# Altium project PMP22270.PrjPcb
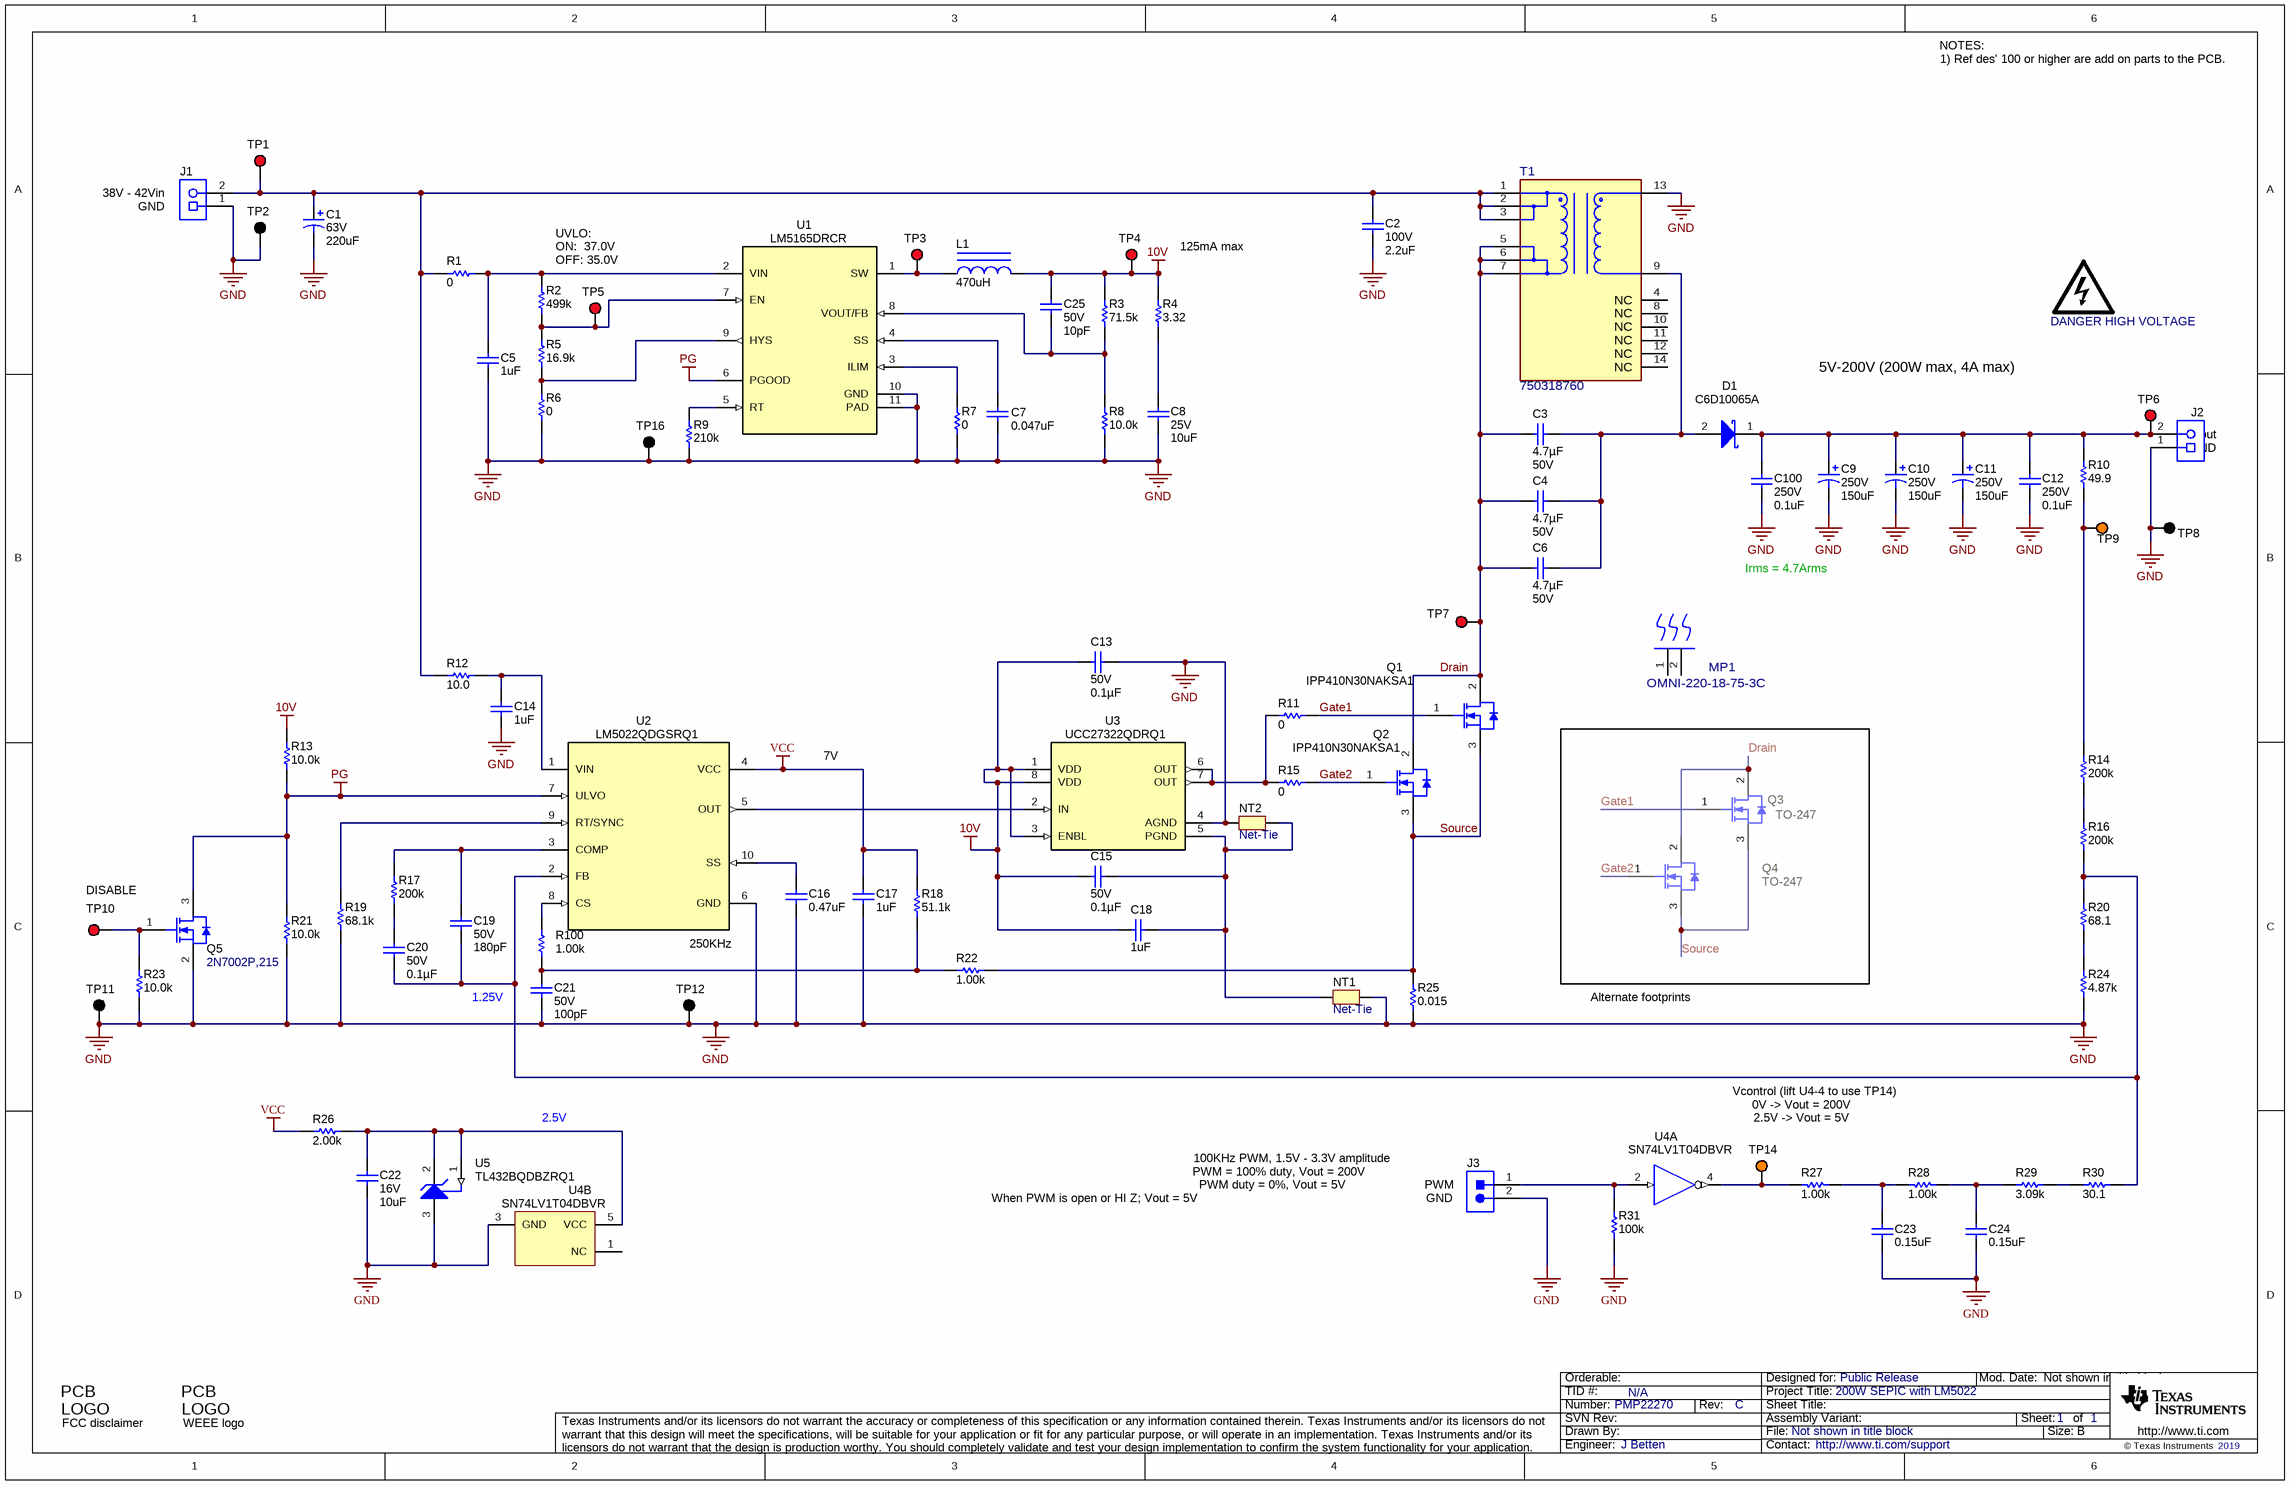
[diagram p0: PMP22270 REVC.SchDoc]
TID: N/A; TechSupport: http://www.ti.com/support; SCH_Rev: C; PRJ_Title: 200W SEPIC with LM5022; PRJ_Number: PMP22270; PRJ_Engineer: J Betten; PRJ_Customer: Public Release; PCB_Rev: A; PCB_Layout: J Betten; CopyrightYear: 2019
1 sheet, 94 parts. Net scope: global (net labels, ports and power ports of the same name join across sheets).
Board file: PMP22270 REVA.PcbDoc

## Sheet PMP22270 REVC.SchDoc
size 431 x 279 mm; Date: Not shown in title block; ApprovedBy: Not shown in title block; CheckedBy: Not shown in title block; Author: Not shown in title block; CompanyName: Not shown in title block; Engineer: Not shown in title block; Organization: Not shown in title block; Address1: Not shown in title block; Address2: Not shown in title block; Address3: Not shown in title block; Address4: Not shown in title block; DocumentNumber: 1; Revision: Use project parameter SCH_Rev; SheetNumber: 1; SheetTotal: 1; PageSetup: Record=PageOptions¦CenterHorizontal=True¦CenterVertical=True¦PrintScale=1.00¦XCorrection=1.00¦YCorrection=1.00¦PrintKind=0¦BorderSize=5000000¦LeftOffset=0¦BottomOffset=0¦Orientation=2¦PaperLength=1000¦PaperWidth=1000¦Scale=100¦PaperSource=15¦PrintQuality=600¦MediaType=1¦DitherType=10¦PaperKind=Letter¦PrintScaleMode=1

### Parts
C1  VDC_V: 63V  ValueDisplayed: 220uF  [SM_RADIAL_H13]  (hidden comment: EEV-FK1J221Q)
C2  VDC_V: 100V  ValueDisplayed: 2.2uF  [1210_250]  (hidden comment: C3225X7R2A225K230AB)
C3  ValueDisplayed: 4.7µF  VDC_V: 50V  [1210_270]  (hidden comment: GCM32ER71H475KA55L)
C4  ValueDisplayed: 4.7µF  VDC_V: 50V  [1210_270]  (hidden comment: GCM32ER71H475KA55L)
C5  ValueDisplayed: 1uF  [1206]  (hidden comment: Capacitor)
C6  ValueDisplayed: 4.7µF  VDC_V: 50V  [1210_270]  (hidden comment: GCM32ER71H475KA55L)
C7  ValueDisplayed: 0.047uF  [0603]  (hidden comment: GRM188R71C473KA01D)
C8  VDC_V: 25V  ValueDisplayed: 10uF  [1206_180]  (hidden comment: GRM31CR71E106KA12L)
C9  VDC_V: 250V  ValueDisplayed: 150uF  [CAPPR7.5-18x31.5]  (hidden comment: EEUED2E151)
C10  VDC_V: 250V  ValueDisplayed: 150uF  [CAPPR7.5-18x31.5]  (hidden comment: EEUED2E151)
C11  VDC_V: 250V  ValueDisplayed: 150uF  [CAPPR7.5-18x31.5]  (hidden comment: EEUED2E151)
C12  VDC_V: 250V  ValueDisplayed: 0.1uF  [1210_220]  (hidden comment: GRM32DR72E104KW01L)
C13  VDC_V: 50V  ValueDisplayed: 0.1µF  [0603]  (hidden comment: C0603C104K5RACAUTO)
C14  ValueDisplayed: 1uF  [1206]  (hidden comment: Capacitor)
C15  VDC_V: 50V  ValueDisplayed: 0.1µF  [0603]  (hidden comment: C0603C104K5RACAUTO)
C16  ValueDisplayed: 0.47uF  [0603]  (hidden comment: Capacitor)
C17  ValueDisplayed: 1uF  [0603]  (hidden comment: Capacitor)
C18  ValueDisplayed: 1uF  [0603]  (hidden comment: Capacitor)
C19  VDC_V: 50V  ValueDisplayed: 180pF  [0603]  (hidden comment: GRM1885C1H181JA01D)
C20  VDC_V: 50V  ValueDisplayed: 0.1µF  [0603]  (hidden comment: C0603C104K5RACAUTO)
C21  VDC_V: 50V  ValueDisplayed: 100pF  [0603]  (hidden comment: GRM1885C1H101JA01D)
C22  VDC_V: 16V  ValueDisplayed: 10uF  [0805_HV]  (hidden comment: GCM21BC71C106KE36L)
C23  ValueDisplayed: 0.15uF  [0603]  (hidden comment: CGA3E3X7R1H154K080AB)
C24  ValueDisplayed: 0.15uF  [0603]  (hidden comment: CGA3E3X7R1H154K080AB)
C25  VDC_V: 50V  ValueDisplayed: 10pF  [0603]  (hidden comment: C1608C0G1H100D080AA)
C100  VDC_V: 250V  ValueDisplayed: 0.1uF  [1210_220]  (hidden comment: GRM32DR72E104KW01L)
D1  C6D10065A  [FP-C6D10065A_TO220-2-MFG]
J1  691214110002  [Wurth_691214110002]  (value not drawn)
J2  691214110002  [Wurth_691214110002]  (value not drawn)
J3  Header_2x1  [CONN_PEC02SAAN]  (value not drawn)
L1  ValueDisplayed: 470uH  [LPS6235]  (hidden comment: Inductor_Iron)
Logo1  FCC disclaimer  [FCC_disclaimer]  (no BOM)
Logo2  WEEE logo  [WEEE_Minimum]  (no BOM)
LOGO?  DANGER HIGH VOLTAGE  [IEC_HighVoltage_Small]  (no BOM)
MP1  OMNI-220-18-75-3C  [FP-OMNI-220-18-75-3C_PTH_HTSNK_75MM0_18MM0-MFG]
NT1  Net-Tie  [Net-Tie_50milWide_30milLong]  (net tie, no BOM)
NT2  Net-Tie  [Net-Tie_20milWide_60milLong]  (net tie, no BOM)
Q1  IPP410N30NAKSA1  [TO-220-3]
Q2  IPP410N30NAKSA1  [TO-220-3]
Q3  IPW65R019C7FKSA1  [TO-247]  (value not drawn)
Q4  IPW65R019C7FKSA1  [TO-247]  (value not drawn)
Q5  2N7002P,215  [SOT-23]
R1  ValueDisplayed: 0  [0603]  (hidden comment: CRCW06030000Z0EA)
R2  ValueDisplayed: 499k  [0603]  (hidden comment: CRCW0603499KFKEA)
R3  ValueDisplayed: 71.5k  [0603]  (hidden comment: CRCW060371K5FKEA)
R4  ValueDisplayed: 3.32  [0603]  (hidden comment: CRCW06033R32FKEA)
R5  ValueDisplayed: 16.9k  [0603]  (hidden comment: CRCW060316K9FKEA)
R6  ValueDisplayed: 0  [0603]  (hidden comment: CRCW06030000Z0EA)
R7  ValueDisplayed: 0  [0603]  (hidden comment: CRCW06030000Z0EA)
R8  ValueDisplayed: 10.0k  [0603]  (hidden comment: Resistor)
R9  ValueDisplayed: 210k  [0603]  (hidden comment: CRCW0603210KFKEA)
R10  value 49.9  [0603]  (hidden comment: Resistor)
R11  ValueDisplayed: 0  [0603]  (hidden comment: CRCW06030000Z0EA)
R12  ValueDisplayed: 10.0  [0603]  (hidden comment: CRCW060310R0FKEA)
R13  ValueDisplayed: 10.0k  [0603]  (hidden comment: CRCW060310K0FKEA)
R14  ValueDisplayed: 200k  [0805_HV]  (hidden comment: CRCW0805200KFKEA)
R15  ValueDisplayed: 0  [0603]  (hidden comment: CRCW06030000Z0EA)
R16  ValueDisplayed: 200k  [0805_HV]  (hidden comment: CRCW0805200KFKEA)
R17  ValueDisplayed: 200k  [0603]  (hidden comment: CRCW0603200KFKEA)
R18  ValueDisplayed: 51.1k  [0603]  (hidden comment: CRCW060351K1FKEA)
R19  ValueDisplayed: 68.1k  [0603]  (hidden comment: CRCW060368K1FKEA)
R20  ValueDisplayed: 68.1  [0603]  (hidden comment: CRCW060368R1FKEA)
R21  ValueDisplayed: 10.0k  [0603]  (hidden comment: CRCW060310K0FKEA)
R22  ValueDisplayed: 1.00k  [0603]  (hidden comment: Resistor)
R23  ValueDisplayed: 10.0k  [0603]  (hidden comment: CRCW060310K0FKEA)
R24  ValueDisplayed: 4.87k  [0603]  (hidden comment: CRCW06034K87FKEA)
R25  ValueDisplayed: 0.015  [2512]  (hidden comment: CSRN2512FK15L0)
R26  ValueDisplayed: 2.00k  [0603]  (hidden comment: CRCW06032K00FKEA)
R27  ValueDisplayed: 1.00k  [0603]  (hidden comment: CRCW06031K00FKEA)
R28  ValueDisplayed: 1.00k  [0603]  (hidden comment: CRCW06031K00FKEA)
R29  ValueDisplayed: 3.09k  [0603]  (hidden comment: CRCW06033K09FKEA)
R30  ValueDisplayed: 30.1  [0603]  (hidden comment: CRCW060330R1FKEA)
R31  ValueDisplayed: 100k  [0603]  (hidden comment: CRCW0603100KFKEA)
R100  ValueDisplayed: 1.00k  [0603]  (hidden comment: CRCW06031K00FKEA)
T1  750318760  [FP-750318760_TRANSFORMER_PTH_14-MFG]
TP1  5000  [Keystone5000]  (value not drawn)
TP2  5001  [Keystone5001]  (value not drawn)
TP3  5000  [Keystone5000]  (value not drawn)
TP4  5000  [Keystone5000]  (value not drawn)
TP5  5000  [Keystone5000]  (value not drawn)
TP6  5000  [Keystone5000]  (value not drawn)
TP7  5000  [Keystone5000]  (value not drawn)
TP8  5001  [Keystone5001]  (value not drawn)
TP9  5003  [Keystone5003]  (value not drawn)
TP10  5000  [Keystone5000]  (value not drawn)
TP11  5001  [Keystone5001]  (value not drawn)
TP12  5001  [Keystone5001]  (value not drawn)
TP14  5003  [Keystone5003]  (value not drawn)
TP16  5001  [Keystone5001]  (value not drawn)
U1  LM5165DRCR  [DRC0010J]
U2  LM5022QDGSRQ1  [DGS0010A_L]
U3  UCC27322QDRQ1  [D0008A_N]
U4  SN74LV1T04DBVR  [DBV0005A_N]  (parts A,B of 2)
U5  TL432BQDBZRQ1  [DBZ0003A_N]

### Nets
10V: C13.1 C15.1 C18.1 C25.1 L1.2 R3.2 R4.2 R13.2 TP4.1 U3.1(VDD) U3.3(ENBL) U3.8(VDD)
GND: C1.2(-) C2.2 C5.2 C7.2 C8.2 C9.2(-) C10.2(-) C11.2(-) C12.2 C13.2 C14.2 C16.2 C17.2 C21.2 C22.2 C23.2 C24.2 C100.2 J1.1 J2.1 J3.2 NT1.1 NT2.1 Q5.2(S) R6.1 R7.1 R8.1 R9.1 R19.1 R21.1 R23.1 R24.1 R25.1 R31.1 T1.13 TP2.1 TP8.1 TP11.1 TP12.1 TP16.1 U1.10(GND) U1.11(PAD) U2.6(GND) U3.4(AGND) U4.3(GND) U5.3(ANODE)
PG: Q5.3(D) R13.1 R21.2 U1.6(PGOOD) U2.7(ULVO)
VCC: C17.1 R18.2 R26.1 U2.4(VCC)
Drain: C3.2 C4.2 C6.2 Q1.2(D) Q2.2(D) Q3.2(D) Q4.2(D) T1.5 T1.6 T1.7 TP7.1
Gate1: Q1.1(G) Q3.1(G) R11.2
Gate2: Q2.1(G) Q4.1(G) R15.2
Source: Q1.3(S) Q2.3(S) Q3.3(S) Q4.3(S) R22.2 R25.2
NetC1_1: C1.1(+) C2.1 J1.2 R1.2 R12.1 T1.1 T1.2 T1.3 TP1.1
NetC3_1: C3.1 C4.1 C6.1 D1.2(A) T1.9
NetC5_1: C5.1 R1.1 R2.2 U1.2(VIN)
NetC7_1: C7.1 U1.4(SS)
NetC8_1: C8.1 R4.1
NetC9_1: C9.1(+) C10.1(+) C11.1(+) C12.1 C100.1 D1.1(K) J2.2 R10.1 TP6.1
NetC14_1: C14.1 R12.2 U2.1(VIN)
NetC15_2: C15.2 C18.2 NT1.2 NT2.2 U3.5(PGND)
NetC16_1: C16.1 U2.10(SS)
NetC19_1: C19.1 R17.2 U2.3(COMP)
NetC19_2: C19.2 C20.2 R16.1 R20.2 R30.2 U2.2(FB)
NetC20_1: C20.1 R17.1
NetC21_1: C21.1 R18.1 R22.1 R100.1
NetC22_1: C22.1 R26.2 U4.5(VCC) U5.1(REF) U5.2(CATHODE)
NetC23_1: C23.1 R27.1 R28.2
NetC24_1: C24.1 R28.1 R29.1
NetC25_2: C25.2 R3.1 R8.2 U1.8(VOUT/FB)
NetJ3_1: J3.1 R31.2 U4.2(A)
NetL1_1: L1.1 TP3.1 U1.1(SW)
NetQ5_1: Q5.1(G) R23.2 TP10.1
NetR2_1: R2.1 R5.2 TP5.1 U1.7(EN)
NetR5_1: R5.1 R6.2 U1.9(HYS)
NetR7_2: R7.2 U1.3(ILIM)
NetR9_2: R9.2 U1.5(RT)
NetR10_2: R10.2 R14.2 TP9.1
NetR11_1: R11.1 R15.1 U3.6(OUT) U3.7(OUT)
NetR14_1: R14.1 R16.2
NetR19_2: R19.2 U2.9(RT/SYNC)
NetR20_1: R20.1 R24.2
NetR27_2: R27.2 TP14.1 U4.4(Y)
NetR29_2: R29.2 R30.1
NetR100_2: R100.2 U2.8(CS)
NetU2_5: U2.5(OUT) U3.2(IN)

Not connected (* = marked no-connect by the designer): MP1 1(MNT_1) 2(MNT_2); T1 4(NC) 8(NC) 10(NC) 11(NC) 12(NC) 14(NC); U4 1(NC)

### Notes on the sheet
- NOTES:
- 1) Ref des' 100 or higher are add on parts to the PCB.
- (near J1) 38V - 42Vin
- (near J1) GND
- UVLO:
- (near R2) ON:  37.0V
- (near R2) OFF: 35.0V
- 125mA max
- 5V-200V (200W max, 4A max)
- (near J2) Vout
- (near J2) GND
- Irms = 4.7Arms
- 7V
- DISABLE
- (near U2) 1MHz
- (near U2) 250KHz
- 1.25V
- Alternate footprints
- 0V -> Vout = 200V
- Vcontrol (lift U4-4 to use TP14)
- 2.5V
- PWM = 100% duty, Vout = 200V
- 100KHz PWM, 1.5V - 3.3V amplitude
- 2.5V -> Vout = 5V
- PWM duty = 0%, Vout = 5V
- When PWM is open or HI Z; Vout = 5V
- (near J3) PWM
- (near J3) GND

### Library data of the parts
C1 = CMP-0011214-2: CAP, AL, 220 uF, 63 V, +/- 20%, 0.16 ohm, AEC-Q200 Grade 2, SMD; Manufacturer: Panasonic; TaMin_C: -55°C; ESR_ohm: 0.16; Polarized: Y; SizeAreaWB_mm2: 263.5; U/M: EA; Value: 220uF; TaMax_C: 105°C; SizeZ_mm: 13.5; SizeX_mm: 15; Cap_Case: H13; SizeArea_mm2: 202.5; CompType: Capacitor; Cap_F: 220µF; IRMS_A: 800mA; AEC Grade: 2; AEC Category: Q200
C2 = CMP-0009152-2: CAP, CERM, 2.2 uF, 100 V, +/- 10%, X7R; Manufacturer: TDK; TaMin_C: -55°C; ESR_ohm: 1.73m; Polarized: N; SizeAreaWB_mm2: 14.7; Value1: 0.00173 ohm; U/M: EA; Value: 2.2uF; TaMax_C: 125°C; SizeZ_mm: 2.5; SizeX_mm: 3.2; SizeArea_mm2: 8; AEC Qualified: Y; Cap_F: 2.2µF; IRMS_A: 5.59317A; AEC Grade: 1; AEC Category: Q200
C3 C4 C6 = CMP-0750153-1: CAP, CERM, 4.7 µF, 50 V,+/- 10%, X7R, AEC-Q200 Grade 1, 1210; Manufacturer: MuRata; Polarized: N; TaMin_C: -55°C; TaMax_C: 125°C; SizeAreaWB_mm2: 14.7; SizeY_mm: 2.5; AEC Category: Q200; Value: 4.7uF; Cap_Case: 1210; AEC Qualified: Y; AEC Grade: 1; SizeArea_mm2: 8; SizeZ_mm: 2.7; U/M: EA; SizeX_mm: 3.2
C5 C14 = CMP-0008711-2: CAP, CERM, 1 uF, 100 V, +/- 20%, X7R, 1206; PartNumber: C3216X7R2A105M160AA; Manufacturer: TDK; Polarized: N; Value: 1uF; U/M: EA; Cap_F: 1µF; Value1: Unknown; VDC_V: 100V; TaMin_C: -55°C; TaMax_C: 125°C; AEC Category: Q200; SizeArea_mm2: 5.12; SizeAreaWB_mm2: 10.92; SizeX_mm: 3.2; SizeY_mm: 1.6; SizeZ_mm: 1.35
C7 = CMP-0007397-4: CAP, CERM, 0.047 uF, 16 V, +/- 10%, X7R, 0603; Manufacturer: MuRata; TaMin_C: -55°C; Polarized: N; SizeAreaWB_mm2: 4.68; Value1: Unknown; U/M: EA; TaMax_C: 125°C; SizeZ_mm: 1; SizeX_mm: 1.6; SizeY_mm: 0.8; Value2: 16V; SizeArea_mm2: 1.28; CompType: Capacitor; Cap_F: 47nF; AEC Category: Q200
C8 = CMP-0008965-2: CAP, CERM, 10 uF, 25 V, +/- 10%, X7R, 1206; Manufacturer: MuRata; TaMin_C: -55°C; Polarized: N; SizeAreaWB_mm2: 10.92; Value1: Unknown; U/M: EA; Value: 10uF; TaMax_C: 125°C; SizeZ_mm: 1.8; SizeX_mm: 3.2; SizeY_mm: 1.6; Cap_Case: 2220; SizeArea_mm2: 5.12; Cap_F: 10µF; AEC Category: Q200
C9-C11 = CMP-0010013-3: CAP, AL, 150 uF, 250 V, +/- 20%, TH; Manufacturer: Panasonic; TaMin_C: -25°C; Polarized: Y; SizeAreaWB_mm2: 400; U/M: EA; Value: 150uF; TaMax_C: 105°C; SizeZ_mm: 31.5; SizeX_mm: 18; AC_Derating: 0.35; SizeArea_mm2: 324; CompType: Capacitor; Cap_F: 150µF; IRMS_A: 1.8A; AEC Category: Q200
C12 C100 = CMP-0009192-2: CAP, CERM, 0.1 uF, 250 V, +/- 10%, X7R, 1210; Manufacturer: MuRata; TaMin_C: -55°C; Polarized: N; SizeAreaWB_mm2: 14.7; Value1: Unknown; U/M: EA; Value: 0.1uF; TaMax_C: 125°C; SizeZ_mm: 2.2; SizeX_mm: 3.2; SizeY_mm: 2.5; Cap_Case: 1210; SizeArea_mm2: 8; Cap_F: 100nF; AEC Category: Q200
C13 C15 C20 = CMP-0079602-1: CAP, CERM, 0.1 µF, 50 V,+/- 10%, X7R, AEC-Q200 Grade 1, 0603; Manufacturer: Kemet; TaMin_C: -55°C; Polarized: N; SizeAreaWB_mm2: 4.68; U/M: EA; Value: 0.1uF; TaMax_C: 125°C; SizeZ_mm: 1; SizeX_mm: 1.6; SizeY_mm: 0.8; SizeArea_mm2: 1.28; CompType: Capacitor; AEC Qualified: Y; Cap_F: 100nF; AEC Category: Q200
C16 = CMP-0007050-4: CAP, CERM, 0.47 uF, 50 V, +/- 10%, X7R, 0603; PartNumber: C1608X7R1H474K080AC; Manufacturer: TDK; Polarized: N; Value: 0.47uF; U/M: EA; Cap_F: 470nF; ESR_ohm: 0.010974; Value1: 0.010974 ohm; VDC_V: 50V; IRMS_A: 1.57483A; TaMin_C: -55°C; TaMax_C: 125°C; AEC Category: Q200; SizeArea_mm2: 1.28; SizeAreaWB_mm2: 4.68; SizeX_mm: 1.6; SizeY_mm: 0.8; SizeZ_mm: 1
C17 C18 = CMP-0007037-4: CAP, CERM, 1 uF, 16 V, +/- 10%, X7R, 0603; PartNumber: C1608X7R1C105K080AC; Manufacturer: TDK; Polarized: N; Value: 1uF; U/M: EA; Cap_F: 1µF; ESR_ohm: 5.7m; Value1: 0.0057 ohm; VDC_V: 16V; TaMin_C: -55°C; TaMax_C: 125°C; AEC Category: Q200; SizeArea_mm2: 1.28; SizeAreaWB_mm2: 4.68; SizeX_mm: 1.6; SizeY_mm: 0.8; SizeZ_mm: 1
C19 = CMP-0007191-4: CAP, CERM, 180 pF, 50 V, +/- 5%, C0G/NP0, 0603; Manufacturer: MuRata; TaMin_C: -55°C; Polarized: N; SizeAreaWB_mm2: 4.68; Value1: Unknown; U/M: EA; Value: 180pF; TaMax_C: 125°C; SizeZ_mm: 1; SizeX_mm: 1.6; SizeY_mm: 0.8; SizeArea_mm2: 1.28; AEC Category: Q200
C21 = CMP-0007171-4: CAP, CERM, 100 pF, 50 V, +/- 5%, C0G/NP0, 0603; Manufacturer: MuRata; TaMin_C: -55°C; Polarized: N; SizeAreaWB_mm2: 4.68; Value1: Unknown; U/M: EA; Value: 100pF; TaMax_C: 125°C; SizeZ_mm: 1; SizeX_mm: 1.6; SizeY_mm: 0.8; SizeArea_mm2: 1.28; AEC Category: Q200
C22 = CMP-0008012-2: CAP, CERM, 10 uF, 16 V, +/- 10%, X7S, AEC-Q200 Grade 1, 0805; Manufacturer: MuRata; TaMin_C: -55°C; Polarized: N; SizeAreaWB_mm2: 6.75; Value1: Unknown; U/M: EA; Value: 10uF; TaMax_C: 125°C; SizeZ_mm: 1.45; SizeX_mm: 2; SizeY_mm: 1.25; Cap_Case: 0805; SizeArea_mm2: 2.5; CompType: Capacitor; AEC Qualified: Y; Cap_F: 10µF; AEC Grade: 1; AEC Category: Q200
C23 C24 = CMP-0007093-5: CAP, CERM, 0.15 uF, 50 V, +/- 10%, X7R, AEC-Q200 Grade 1, 0603; Manufacturer: TDK; TaMin_C: -55°C; ESR_ohm: 0.028863; Polarized: N; SizeAreaWB_mm2: 4.68; Value1: 0.028863 ohm; U/M: EA; Value: 0.15uF; TaMax_C: 125°C; SizeZ_mm: 1; SizeX_mm: 1.6; SizeY_mm: 0.8; Value2: 50V; SizeArea_mm2: 1.28; CompType: Capacitor; AEC Qualified: Y; Cap_F: 150nF; IRMS_A: 9.78809dA; AEC Category: Q200
C25 = CMP-0006988-4: CAP, CERM, 10 pF, 50 V, +/- 5%, C0G/NP0, 0603; Manufacturer: TDK; TaMin_C: -55°C; ESR_ohm: 0.3492; Polarized: N; SizeAreaWB_mm2: 4.68; Value1: 0.3492 ohm; U/M: EA; Value: 10pF; TaMax_C: 125°C; SizeZ_mm: 1; SizeX_mm: 1.6; SizeY_mm: 0.8; SizeArea_mm2: 1.28; AEC Category: Q200
D1 = CMP-0087641-2: Diode Silicon Carbide Schottky 650V 37A (DC) Through Hole TO-220-2; Manufacturer: Cree; SizeZ_mm: 19.431mm; TJmax_C: 175°C; AEC Category: Q101; AEC Qualified: No; Symbol Name: SYM-C6D10065A
J1 J2 = CMP-0054825-2: Terminal Block, 3.5mm, 2x1, Tin, TH; Manufacturer: Wurth Elektronik; Pitch_mm: 3.5; CT: TRUE; CNHeader: FALSE; Voltage_V: 300V; Gender: Female; Cert_UL: Y; Row_Count: 1; Current_A: 10A
J3 = CMP-0002337-1: Header, 100mil, 2x1, Tin, TH; PartNumber: PEC02SAAN; Manufacturer: Sullins Connector Solutions; Cert_UL: Y; CNHeader: TRUE; CT: FALSE; Current_A: 3A; Gender: Male; Green_Lifecycle: Not Set; Green_REACh: Incomplete; Pitch_mm: 2.54; Row_Count: 1; Shrouded: N; Voltage_V: 1.8kV
L1 = CMP-0061837-2: Inductor, Shielded Drum Core, Ferrite, 470 uH, 0.26 A, 1.6 ohm, SMD; PartNumber: LPS6235-474MLB; Manufacturer: Coilcraft; Value: 470uH; Ind_H: 470µH; Imax_A: 260mA; Irms: 0.43A @ 40C rise; Isat: 0.26A @ 30% inductance drop; DCR_ohm: 1.6; Value1: 1.6 ohm; Value2: 0.26A; SizeAreaWB_mm2: 64; SizeArea_mm2: 36; SizeX_mm: 6; SizeZ_mm: 3.5; AEC Category: Q200; Green_Lifecycle: Not Set; Green_REACh: Incomplete
Logo1 = CMP-0074847-1: FCC_disclaimer; Library Reference: Logo
Logo2 = CMP-0074769-1
LOGO? = CMP-0074835-1: IEC 61010-1 High Voltage Warning; SymbolCreator: a0412235
MP1 = CMP-0086954-1: OmniKlip Heat Sink w/3 clips, 18mm wide, 75mm long, black anodized for TO-220; Manufacturer: Wakefield-Vette
NT1 NT2 = CMP-0078142-3: Single point connection between nets.
Q1 Q2 = CMP-0085354-1: MOSFET, N-CH, 300 V, 44 A, TO-220-3; Alternate Manufacturer: None; Manufacturer: Infineon Technologies; SizeAreaWB_mm2: 127.3152; IdsMax_A: 44A; VdsMax_V: 300V; Vgs_V: 20V; Value2: 65 nC; SizeZ_mm: 20.68; AEC Category: Q101; Value: 300V; ChType: N; Value1: ? ohm; SizeY_mm: 10.16; QgTyp_nC: 65; SizeArea_mm2: 86.0552; ChMode: Enhancement; SizeX_mm: 8.47
Q3 Q4 = CMP-0001229-3: MOSFET, N-CH, 700 V, 0.019 Ohm, TO-247; Alternate Manufacturer: None; Manufacturer: Infineon Technologies; SizeZ_mm: 25; ChType: N; Value2: 215 nC; VdsMax_V: 700V; SizeX_mm: 15.6; SizeY_mm: 5; Vgs_V: 20V; Value: 700V; SizeArea_mm2: 78; AEC Category: Q101; IdsMax_A: 62A; SizeAreaWB_mm2: 123.2; QgTyp_nC: 215; ChMode: Enhancement
Q5 = CMP-0000775-2: MOSFET, N-CH, 60 V, 0.36 A, SOT-23; Alternate Manufacturer: None; Manufacturer: Nexperia; SizeZ_mm: 1.1; ChType: N; Value2: 0.6 nC; VdsMax_V: 60V; SizeX_mm: 2.5; SizeY_mm: 3; Vgs_V: 20V; Value: 60V; Rdson45_ohm: 2; SizeArea_mm2: 7.5; AEC Category: Q101; IdsMax_A: 360mA; SizeAreaWB_mm2: 14; QgTyp_nC: 0.6
R1 R6 R7 R11 R15 = CMP-0025697-4: RES, 0, 5%, 0.1 W, AEC-Q200 Grade 0, 0603; Manufacturer: Vishay-Dale; Power_W: 100mW; TempCo: 200 ppm/C; Value_Code: 0000; Value: 0; EIA_Code: E24; SizeX_mm: 1.6; SizeY_mm: 0.8; SizeZ_mm: 1; Value2: 0.1W; SizeArea_mm2: 1.28; AEC Qualified: Y; VDC_V: 75V; AEC Category: Q200
R2 = CMP-0022445-4: RES, 499 k, 1%, 0.1 W, AEC-Q200 Grade 0, 0603; Manufacturer: Vishay-Dale; Power_W: 100mW; TempCo: 100 ppm/C; Value: 499k; EIA_Code: E96; SizeX_mm: 1.6; SizeY_mm: 0.8; SizeZ_mm: 1; Value2: 0.1W; SizeArea_mm2: 1.28; AEC Qualified: Y; VDC_V: 75V; AEC Category: Q200; AEC Grade: 0
R3 = CMP-0022581-4: RES, 71.5 k, 1%, 0.1 W, AEC-Q200 Grade 0, 0603; Manufacturer: Vishay-Dale; Power_W: 100mW; TempCo: 100 ppm/C; Value_Code: 71k5; Value: 71.5k; EIA_Code: E96; SizeX_mm: 1.6; SizeY_mm: 0.8; SizeZ_mm: 1; Value2: 0.1W; SizeArea_mm2: 1.28; AEC Qualified: Y; VDC_V: 75V; AEC Category: Q200; AEC Grade: 0
R4 = CMP-0022400-4: RES, 3.32, 1%, 0.1 W, AEC-Q200 Grade 0, 0603; Manufacturer: Vishay-Dale; Power_W: 100mW; TempCo: 100 ppm/C; Value_Code: 3R32; Value: 3.32; EIA_Code: E96; SizeX_mm: 1.6; SizeY_mm: 0.8; SizeZ_mm: 1; Value2: 0.1W; SizeArea_mm2: 1.28; AEC Qualified: Y; VDC_V: 75V; AEC Category: Q200; AEC Grade: 0
R5 = CMP-0022081-4: RES, 16.9 k, 1%, 0.1 W, AEC-Q200 Grade 0, 0603; Manufacturer: Vishay-Dale; Power_W: 100mW; TempCo: 100 ppm/C; Value_Code: 16k9; Value: 16.9k; EIA_Code: E96; SizeX_mm: 1.6; SizeY_mm: 0.8; SizeZ_mm: 1; Value2: 0.1W; SizeArea_mm2: 1.28; AEC Qualified: Y; VDC_V: 75V; AEC Category: Q200; AEC Grade: 0
R8 = CMP-0021998-4: RES, 10.0 k, 1%, 0.1 W, AEC-Q200 Grade 0, 0603; PartNumber: CRCW060310K0FKEA; Manufacturer: Vishay-Dale; Value: 10.0k; Res_ohm: 10k; Value_Code: 10k0; Power_W: 100mW; Value2: 0.1W; VDC_V: 75V; TempCo: 100 ppm/C; EIA_Code: E96; AEC Category: Q200; AEC Qualified: Y; AEC Grade: 0; SizeArea_mm2: 1.28; SizeX_mm: 1.6; SizeY_mm: 0.8; SizeZ_mm: 1
R9 = CMP-0022208-4: RES, 210 k, 1%, 0.1 W, AEC-Q200 Grade 0, 0603; Manufacturer: Vishay-Dale; Power_W: 100mW; TempCo: 100 ppm/C; Value: 210k; EIA_Code: E96; SizeX_mm: 1.6; SizeY_mm: 0.8; SizeZ_mm: 1; Value2: 0.1W; SizeArea_mm2: 1.28; AEC Qualified: Y; VDC_V: 75V; AEC Category: Q200; AEC Grade: 0
R10 = CMP-0022448-4: RES, 49.9, 1%, 0.1 W, AEC-Q200 Grade 0, 0603; PartNumber: CRCW060349R9FKEA; Manufacturer: Vishay-Dale; Value_Code: 49R9; Power_W: 100mW; Value2: 0.1W; VDC_V: 75V; TempCo: 100 ppm/C; EIA_Code: E96; AEC Category: Q200; AEC Grade: 0; AEC Qualified: Y; SizeArea_mm2: 1.28; SizeX_mm: 1.6; SizeY_mm: 0.8; SizeZ_mm: 1
R12 = CMP-0022003-4: RES, 10.0, 1%, 0.1 W, AEC-Q200 Grade 0, 0603; Manufacturer: Vishay-Dale; Power_W: 100mW; TempCo: 100 ppm/C; Value_Code: 10R0; Value: 10.0; EIA_Code: E96; Res_ohm: 10; SizeX_mm: 1.6; SizeY_mm: 0.8; SizeZ_mm: 1; Value2: 0.1W; SizeArea_mm2: 1.28; AEC Qualified: Y; VDC_V: 75V; AEC Category: Q200; AEC Grade: 0
R13 R21 R23 = CMP-0021998-4: RES, 10.0 k, 1%, 0.1 W, AEC-Q200 Grade 0, 0603; Manufacturer: Vishay-Dale; Power_W: 100mW; TempCo: 100 ppm/C; Value_Code: 10k0; Value: 10.0k; EIA_Code: E96; Res_ohm: 10k; SizeX_mm: 1.6; SizeY_mm: 0.8; SizeZ_mm: 1; Value2: 0.1W; SizeArea_mm2: 1.28; AEC Qualified: Y; VDC_V: 75V; AEC Category: Q200; AEC Grade: 0
R14 R16 = CMP-0021038-3: RES, 200 k, 1%, 0.125 W, AEC-Q200 Grade 0, 0805; Manufacturer: Vishay-Dale; Power_W: 125mW; TempCo: 100 ppm/C; Value: 200k; EIA_Code: E96; SizeX_mm: 2; SizeY_mm: 1.25; SizeZ_mm: 1.45; Value2: 0.125W; SizeArea_mm2: 2.5; AEC Qualified: Y; VDC_V: 150V; AEC Category: Q200; AEC Grade: 0
R17 = CMP-0022200-4: RES, 200 k, 1%, 0.1 W, AEC-Q200 Grade 0, 0603; Manufacturer: Vishay-Dale; Power_W: 100mW; TempCo: 100 ppm/C; Value: 200k; EIA_Code: E96; SizeX_mm: 1.6; SizeY_mm: 0.8; SizeZ_mm: 1; Value2: 0.1W; SizeArea_mm2: 1.28; AEC Qualified: Y; VDC_V: 75V; AEC Category: Q200; AEC Grade: 0
R18 = CMP-0022482-4: RES, 51.1 k, 1%, 0.1 W, AEC-Q200 Grade 0, 0603; Manufacturer: Vishay-Dale; Power_W: 100mW; TempCo: 100 ppm/C; Value_Code: 51k1; Value: 51.1k; EIA_Code: E96; SizeX_mm: 1.6; SizeY_mm: 0.8; SizeZ_mm: 1; Value2: 0.1W; SizeArea_mm2: 1.28; AEC Qualified: Y; VDC_V: 75V; AEC Category: Q200; AEC Grade: 0
R19 = CMP-0022552-4: RES, 68.1 k, 1%, 0.1 W, AEC-Q200 Grade 0, 0603; Manufacturer: Vishay-Dale; Power_W: 100mW; TempCo: 100 ppm/C; Value_Code: 68k1; Value: 68.1k; EIA_Code: E96; SizeX_mm: 1.6; SizeY_mm: 0.8; SizeZ_mm: 1; Value2: 0.1W; SizeArea_mm2: 1.28; AEC Qualified: Y; VDC_V: 75V; AEC Category: Q200; AEC Grade: 0
R20 = CMP-0022553-4: RES, 68.1, 1%, 0.1 W, AEC-Q200 Grade 0, 0603; Manufacturer: Vishay-Dale; Power_W: 100mW; TempCo: 100 ppm/C; Value_Code: 68R1; Value: 68.1; EIA_Code: E96; SizeX_mm: 1.6; SizeY_mm: 0.8; SizeZ_mm: 1; Value2: 0.1W; SizeArea_mm2: 1.28; AEC Qualified: Y; VDC_V: 75V; AEC Category: Q200; AEC Grade: 0
R22 = CMP-0022109-5: RES, 1.00 k, 1%, 0.1 W, AEC-Q200 Grade 0, 0603; PartNumber: CRCW06031K00FKEA; Manufacturer: Vishay-Dale; Value: 1.00k; Res_ohm: 1k; Value_Code: 1k00; Power_W: 100mW; Value2: 0.1W; VDC_V: 75V; TempCo: 100 ppm/C; EIA_Code: E96; AEC Category: Q200; AEC Qualified: Y; AEC Grade: 0; SizeArea_mm2: 1.28; SizeX_mm: 1.6; SizeY_mm: 0.8; SizeZ_mm: 1
R24 = CMP-0022457-4: RES, 4.87 k, 1%, 0.1 W, AEC-Q200 Grade 0, 0603; Manufacturer: Vishay-Dale; Power_W: 100mW; TempCo: 100 ppm/C; Value_Code: 4k87; Value: 4.87k; EIA_Code: E96; SizeX_mm: 1.6; SizeY_mm: 0.8; SizeZ_mm: 1; Value2: 0.1W; SizeArea_mm2: 1.28; AEC Qualified: Y; VDC_V: 75V; AEC Category: Q200; AEC Grade: 0
R25 = CMP-0015772-2: RES, 0.015, 1%, 2 W, 2512; Manufacturer: Stackpole Electronics Inc; Power_W: 2W; TempCo: 200 ppm/C; Value_Code: R015; U/M: EA; Value: 0.015; EIA_Code: E96; SizeX_mm: 6.3; SizeY_mm: 3.2; SizeZ_mm: 0.71; SizeArea_mm2: 20.16; AEC Category: Q200
R26 = CMP-0022268-4: RES, 2.00 k, 1%, 0.1 W, AEC-Q200 Grade 0, 0603; Manufacturer: Vishay-Dale; Power_W: 100mW; TempCo: 100 ppm/C; Value_Code: 2k00; Value: 2.00k; EIA_Code: E96; Res_ohm: 2k; SizeX_mm: 1.6; SizeY_mm: 0.8; SizeZ_mm: 1; Value2: 0.1W; SizeArea_mm2: 1.28; AEC Qualified: Y; VDC_V: 75V; AEC Category: Q200; AEC Grade: 0
R27 R28 R100 = CMP-0022109-5: RES, 1.00 k, 1%, 0.1 W, AEC-Q200 Grade 0, 0603; Manufacturer: Vishay-Dale; Power_W: 100mW; TempCo: 100 ppm/C; Value_Code: 1k00; Value: 1.00k; EIA_Code: E96; Res_ohm: 1k; SizeX_mm: 1.6; SizeY_mm: 0.8; SizeZ_mm: 1; Value2: 0.1W; SizeArea_mm2: 1.28; AEC Qualified: Y; VDC_V: 75V; AEC Category: Q200; AEC Grade: 0
R29 = CMP-0022372-4: RES, 3.09 k, 1%, 0.1 W, AEC-Q200 Grade 0, 0603; Manufacturer: Vishay-Dale; Power_W: 100mW; TempCo: 100 ppm/C; Value_Code: 3k09; Value: 3.09k; EIA_Code: E96; SizeX_mm: 1.6; SizeY_mm: 0.8; SizeZ_mm: 1; Value2: 0.1W; SizeArea_mm2: 1.28; AEC Qualified: Y; VDC_V: 75V; AEC Category: Q200; AEC Grade: 0
R30 = CMP-0022326-4: RES, 30.1, 1%, 0.1 W, AEC-Q200 Grade 0, 0603; Manufacturer: Vishay-Dale; Power_W: 100mW; TempCo: 100 ppm/C; Value_Code: 30R1; Value: 30.1; EIA_Code: E96; SizeX_mm: 1.6; SizeY_mm: 0.8; SizeZ_mm: 1; Value2: 0.1W; SizeArea_mm2: 1.28; AEC Qualified: Y; VDC_V: 75V; AEC Category: Q200; AEC Grade: 0
R31 = CMP-0021990-4: RES, 100 k, 1%, 0.1 W, AEC-Q200 Grade 0, 0603; Manufacturer: Vishay-Dale; Power_W: 100mW; TempCo: 100 ppm/C; Value: 100k; EIA_Code: E96; SizeX_mm: 1.6; SizeY_mm: 0.8; SizeZ_mm: 1; Value2: 0.1W; SizeArea_mm2: 1.28; AEC Qualified: Y; VDC_V: 75V; AEC Category: Q200; AEC Grade: 0
T1 = CMP-0088074-1: TRANSFORMER, 25uH, 1:1 turn ratio; Manufacturer: Wurth Electronics; Rsec1_ohm: 0.035; DCR_ohm: 8m; AEC Qualified: No; SizeZ_mm: 30.48mm; Ind_H: 25µH
TP1 TP3-TP7 TP10 = CMP-0055137-1: Test Point, Miniature, Red, TH; Manufacturer: Keystone; ContactFinish: Silver; CNHeader: FALSE; CT: TRUE; Green_Lifecycle: Active; Green_REACh: Passed
TP2 TP8 TP11 TP12 TP16 = CMP-0055138-1: Test Point, Miniature, Black, TH; Manufacturer: Keystone; ContactFinish: Silver; CNHeader: FALSE; CT: TRUE; Green_Lifecycle: Active; Green_REACh: Passed
TP9 TP14 = CMP-0055140-1: Test Point, Miniature, Orange, TH; Manufacturer: Keystone; CNHeader: FALSE; ContactFinish: Silver; CT: TRUE; Green_Lifecycle: Active; Green_REACh: Passed
U1 = CMP-0076321-6: 3V-65V, 150mA Synchronous Buck Converter With Ultra-Low IQ, DRC0010J (VSON-10); Alternate PartNumber: LM5165DRCT; Manufacturer: Texas Instruments; SizeX_mm: 3; Rating: Catalog; CompType: IC; AEC Category: Q200; SizeZ_mm: 1; SizeAreaWB_mm2: 16; SizeArea_mm2: 9; AEC Qualified: N
U2 = CMP-0076391-1: 2.2MHz 60-V Low Side Controller for Boost, SEPIC and Flyback, DGS0010A (VSSOP-10); Manufacturer: Texas Instruments; Alternate PartNumber: LM5022QDGSTQ1; SizeAreaWB_mm2: 23.6; SizeArea_mm2: 14.7; SizeZ_mm: 1.1; SizeY_mm: 3.0; U/M: EA; CompType: IC; SizeX_mm: 4.9
U3 = CMP-0073898-1: Automotive Catalog Single 9-A High Speed Low-Side MOSFET Driver With Enable, D0008A (SOIC-8); Alternate Manufacturer: Texas Instruments; SizeAreaWB_mm2: 56.58; U/M: EA; SizeZ_mm: 1.75; SizeX_mm: 4.9; SizeY_mm: 6.2; SizeArea_mm2: 30.38; CompType: IC
U4 = CMP-0051667-2: Single Power Supply INVERTER Gate logic level shifter, DBV0005A (SOT-23-5); Manufacturer: Texas Instruments; Rating: Catalog; ICC @ Nom Voltage(Max)(mA): 0.01; Input Type: TTL; Schmitt Trigger: No; VCC(Max)(V): 5.5; tpd @ Nom Voltage(Max)(ns): 13,7.5,5.5,7.0; Special Features: 1.8V to 3.3V Up Translation,3.3V to 1.8V Down Translation,5V Input Tolerant; Logic: Inverting; 3-State Output: Yes; F @ Nom Voltage(Max)(Mhz): 50; Voltage(Nom)(V): 1.8,2.5,3.3,5.5; Output Type: CMOS; VCC(Min)(V): 1.6; Bits(#): 1; Output Drive (IOL/IOH)(Max)(mA): 8/-8; AEC Category: Q200; AEC Qualified: N; CompType: IC; SizeAreaWB_mm2: 14.82; SizeArea_mm2: 8.12; SizeX_mm: 2.8; SizeY_mm: 2.9; SizeZ_mm: 1.45
U5 = CMP-0032978-1: Automotive Catalog Adjustable Precision Shunt Regulator, 34 ppm / degC, 100 mA, -40 to 125 degC, 3-pin SOT-23 (DBZ), Green (RoHS & no Sb/Br); Manufacturer: Texas Instruments; VO Adj(Min)(V): 2.495; Temp Coeff(Typ)(ppm/ degree C): 34; SubFamily: Shunt Voltage Reference; Initial Accuracy @ 25/deg C(%): 0.5; Min Iz for Regulation(uA): 600; VO Adj(Max)(V): 36; Iout/Iz(Max)(mA): 100

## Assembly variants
001: not fitted C? Q3 Q4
